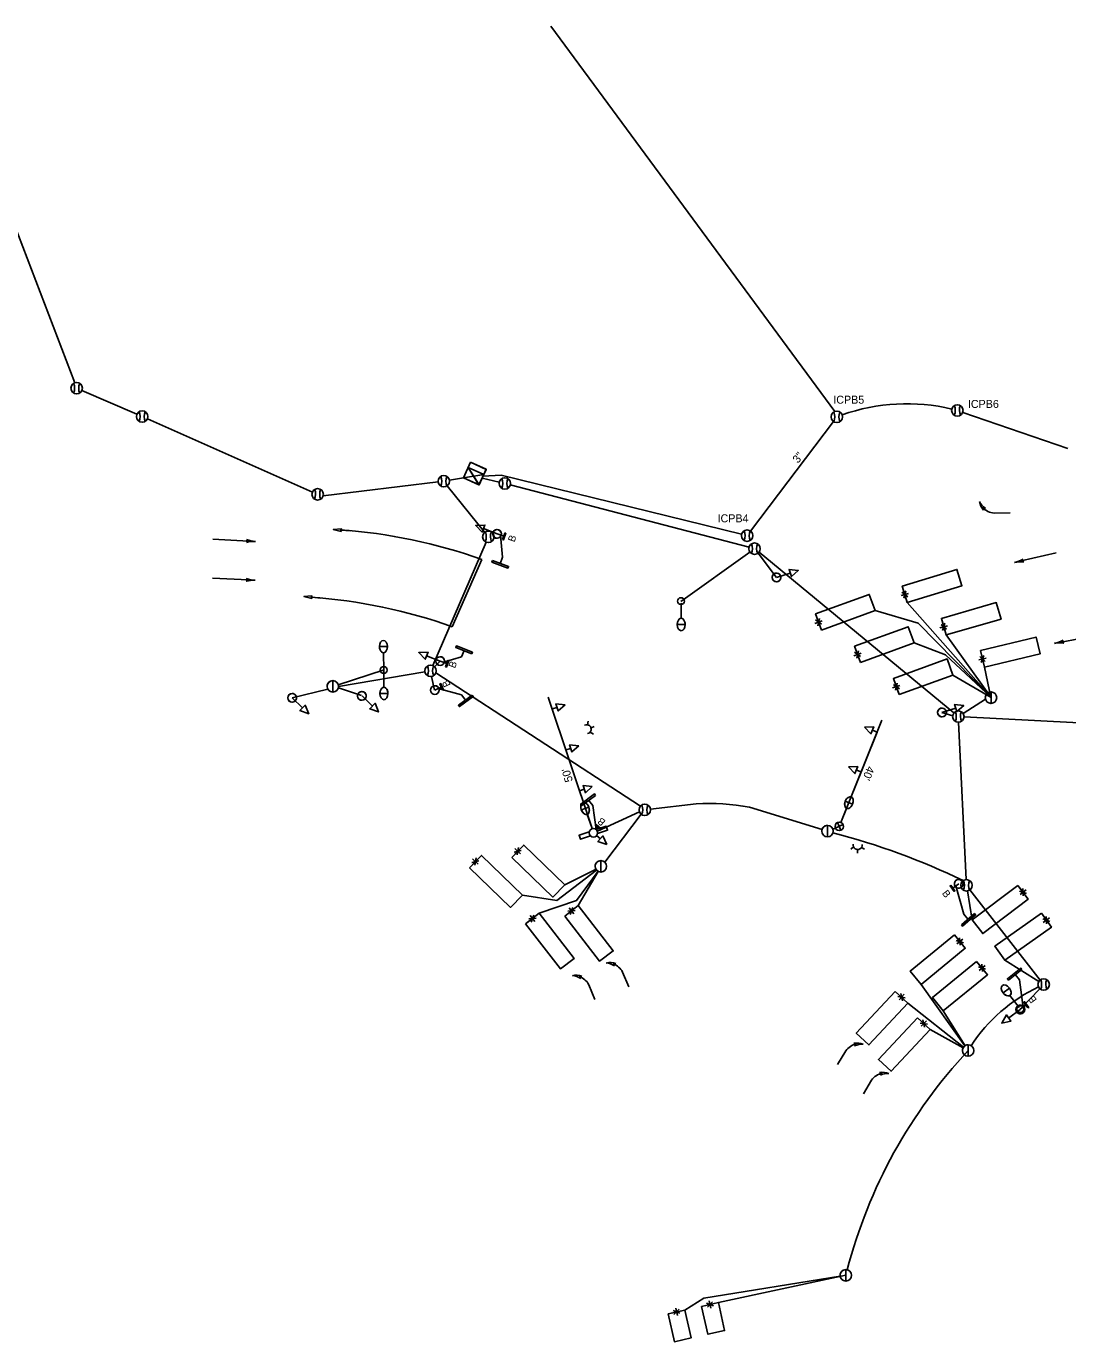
# Model space of a CAD drawing. Extents: x 596176 to 605330, y 332416 to 402398.
# Drawn here: x 603963.9 to 604328.3, y 349684.1 to 350144.4 of the extents above; entities that cross this region are included whole.
import ezdxf

# ---------------------------------------------------------------- set-up
doc = ezdxf.new("R2010")
doc.units = 0
for name, color, linetype in [('P_LTG', 7, 'Continuous'), ('P_SIG', 7, 'Continuous'), ('P_SIG_Bold', 7, 'Continuous'), ('P_SIG_Conduit', 7, 'Continuous'), ('P_SIG_IC', 7, 'Continuous'), ('P_SIG_Loops', 7, 'Continuous'), ('P_SIG_SignalHeads', 7, 'Continuous')]:
    doc.layers.add(name, color=color, linetype=linetype)

# ---------------------------------------------------------------- blocks, each defined once
blk = doc.blocks.new('_U260')
at = {"layer": 'P_SIG'}
blk.add_line((-0.385, 0.001), (0, 0), dxfattribs=at)
for points in [[(-0.611, 0.001), (-0.385, 0.101), (-0.385, -0.1), (-0.611, 0.001)], [(-0.385, 0.101), (-0.611, 0.001), (-0.385, -0.1), (-0.385, 0.101)], [(-0.611, 0.001), (-0.385, 0.101), (-0.385, -0.1), (-0.611, 0.001)]]:
    blk.add_lwpolyline(points, dxfattribs=at)
blk = doc.blocks.new('_U244')
at = {"layer": 'P_SIG'}
blk.add_circle((0, 0), 0.116, dxfattribs=at)
for start, end in [(0, 180), (180, 0)]:
    blk.add_arc((0, 0), 0.116, start, end, dxfattribs=at)
blk = doc.blocks.new('_U247')
at = {"layer": 'P_SIG_Bold'}
for p, q in [((-3.048, 0), (-0.114, 0)), ((-0.081, 0.081), (0.081, -0.081)), ((0.081, 0.081), (-0.081, -0.081))]:
    blk.add_line(p, q, dxfattribs=at)
blk.add_circle((0, 0), 0.114, dxfattribs=at)
blk.add_text("40'", height=0.2134, dxfattribs=at).set_placement((-1.787, 0.092))
blk = doc.blocks.new('_U248')
at = {"layer": 'P_SIG_Bold'}
blk.add_line((-0.114, 0), (-3.81, 0), dxfattribs=at)
for points in [[(-0.057, 0.098), (-0.057, 0.38), (0.058, 0.38), (0.058, 0.098)], [(0.058, -0.1), (0.058, -0.382), (-0.057, -0.382), (-0.057, -0.1)]]:
    blk.add_lwpolyline(points, dxfattribs=at)
blk.add_circle((0.001, -0.001), 0.114, dxfattribs=at)
at = {"layer": 'P_SIG'}
blk.add_text("50'", height=0.2134, rotation=178.0381, dxfattribs=at).set_placement((-1.484, -0.08))
blk = doc.blocks.new('LUMINAIRES_1')
at = {"layer": 'P_LTG'}
for p, q in [((4.3, 25.1), (-4.1, 25.1)), ((0, 2.3), (0, 18.4))]:
    blk.add_line(p, q, dxfattribs=at)
blk.add_circle((0, 0.1), 3.68, dxfattribs=at)
blk.add_ellipse((0.1, 25.1), major_axis=(0, 6.65), ratio=0.636439, dxfattribs=at)
blk.add_ellipse((0.1, 25.1), major_axis=(0, 6.65), ratio=0.636439, start_param=1.570796, end_param=4.712389, dxfattribs=at)
blk = doc.blocks.new('_U249')
at = {"layer": 'P_LTG'}
for p, q in [((4.3, 25.1), (-4.1, 25.1)), ((0, 2.3), (0, 18.4))]:
    blk.add_line(p, q, dxfattribs=at)
blk.add_ellipse((0.1, 25.1), major_axis=(0, 6.65), ratio=0.636439, dxfattribs=at)
blk.add_ellipse((0.1, 25.1), major_axis=(0, 6.65), ratio=0.636439, start_param=1.570796, end_param=4.712389, dxfattribs=at)
blk = doc.blocks.new('HEAD - TEMPORARY_2')
at = {"layer": 'P_SIG'}
blk.add_line((0.135, 0), (0, 0), dxfattribs=at)
blk.add_lwpolyline([(0.36, 0), (0.135, -0.1), (0.135, 0.1)], close=True, dxfattribs=at)
blk = doc.blocks.new('PUSH BUTTON')
at = {"layer": 'P_SIG'}
blk.add_line((0, 0), (7.6, 0), dxfattribs=at)
blk.add_lwpolyline([(7.6, -3.7), (7.6, 3.7), (8.6, 3.7), (8.6, -3.7)], close=True, dxfattribs=at)
blk.add_text('B', height=7.68, rotation=90, dxfattribs=at).set_placement((20.6, -2.6))
blk = doc.blocks.new('CONTROL CABINET_3')
at = {"layer": 'P_SIG'}
for p, q in [((-0.114, 0.076), (0.114, 0.076)), ((-0.114, 0.076), (0.114, -0.076)), ((0.114, 0.076), (-0.114, -0.076))]:
    blk.add_line(p, q, dxfattribs=at)
blk.add_lwpolyline([(-0.114, 0.152), (0.114, 0.152), (0.114, -0.076), (-0.114, -0.076)], close=True, dxfattribs=at)
blk = doc.blocks.new('_U256')
at = {"layer": 'P_SIG_Loops'}
for p, q in [((-0.055, -0.084), (0.052, 0.081)), ((0.056, -0.083), (-0.053, 0.082)), ((0, 0), (0, -0.229)), ((-0.105, -0.001), (0.099, -0.001))]:
    blk.add_line(p, q, dxfattribs=at)
blk.add_lwpolyline([(0, -0.229), (1.524, -0.229), (1.524, 0.229), (0, 0.229)], close=True, dxfattribs=at)
blk = doc.blocks.new('_U257')
at = {"layer": 'P_SIG_Loops'}
for p, q in [((-0.055, -0.084), (0.052, 0.081)), ((0.056, -0.083), (-0.053, 0.082)), ((-0.105, -0.001), (0.099, -0.001))]:
    blk.add_line(p, q, dxfattribs=at)
blk.add_lwpolyline([(0, -0.229), (0.762, -0.229), (0.762, 0.229), (0, 0.229)], close=True, dxfattribs=at)
blk = doc.blocks.new('_U212')
at = {"layer": 'P_SIG'}
blk.add_circle((0, 0), 6.1, dxfattribs=at)
for centre, start, end in [((-15.5, 0.1), 336.6741, 22.5272), ((15.5, 0.1), 157.5751, 203.4282)]:
    blk.add_arc(centre, 13.3, start, end, dxfattribs=at)
blk = doc.blocks.new('_U211')
at = {"layer": 'P_SIG'}
blk.add_line((0, 6.1), (0, -6.1), dxfattribs=at)
blk.add_lwpolyline([(0, -6.1), (0, 6.1)], dxfattribs=at)
blk.add_circle((0, 0), 6.1, dxfattribs=at)
for start, end in [(89.7008, 180), (180, 269.7008)]:
    blk.add_arc((0, 0), 6.1, start, end, dxfattribs=at)
blk = doc.blocks.new('_U269')
at = {"layer": 'P_SIG'}
blk.add_line((-0.017, -0.02), (-0.975, -0.02), dxfattribs=at)
blk.add_lwpolyline([(-0.914, 0.018), (-0.975, -0.02), (-0.914, -0.058)], dxfattribs=at)
for centre, start, end in [((-1.158, 0.78), 270, 287.7623), ((-1.158, -0.819), 72.2377, 90)]:
    blk.add_arc(centre, 0.799, start, end, dxfattribs=at)
blk = doc.blocks.new('_U268')
at = {"layer": 'P_SIG'}
for p, q in [((-0.675, 0.115), (-0.743, 0.129)), ((-0.725, 0.057), (-0.743, 0.129)), ((-0.017, -0.02), (-0.443, -0.02))]:
    blk.add_line(p, q, dxfattribs=at)
for centre, radius, start, end in [((-0.479, 0.454), 0.392, 205.2667, 239.9151), ((-0.377, 0.361), 0.462, 189.3153, 221.1715), ((-0.412, 0.421), 0.442, 221.4708, 266.0347)]:
    blk.add_arc(centre, radius, start, end, dxfattribs=at)
blk = doc.blocks.new('_U270')
at = {"layer": 'P_SIG'}
for p, q in [((-0.725, -0.096), (-0.743, -0.168)), ((-0.675, -0.154), (-0.743, -0.168)), ((-0.017, -0.02), (-0.443, -0.02))]:
    blk.add_line(p, q, dxfattribs=at)
for centre, radius, start, end in [((-0.377, -0.401), 0.462, 138.8285, 170.6847), ((-0.479, -0.493), 0.392, 120.0849, 154.7333), ((-0.412, -0.46), 0.442, 93.9653, 138.5292)]:
    blk.add_arc(centre, radius, start, end, dxfattribs=at)
blk = doc.blocks.new('CONFIRMATION LIGHT_1')
at = {"layer": 'P_SIG'}
for p, q in [((-4.2, 3), (-7.5, 4.8)), ((0, 5.5), (0, 9.2)), ((4.3, 2.9), (7.3, 5.5))]:
    blk.add_line(p, q, dxfattribs=at)
blk.add_arc((0, 0.6), 4.81, 352.2462, 187.7538, dxfattribs=at)
blk = doc.blocks.new('_U280')
at = {"layer": 'P_LTG'}
for p, q in [((4.3, 25), (-4.2, 25)), ((0, 0), (0, 18.5)), ((0, 0), (0, -18.3)), ((-4.3, -25), (4.2, -25))]:
    blk.add_line(p, q, dxfattribs=at)
blk.add_circle((0, 0), 3.68, dxfattribs=at)
for centre, major_axis in [((0, 25), (0, 6.65)), ((0, -25), (0, -6.65))]:
    blk.add_ellipse(centre, major_axis=major_axis, ratio=0.636439, dxfattribs=at)
for centre, major_axis in [((0, 25), (0, 6.65)), ((0, -25), (0, -6.65))]:
    blk.add_ellipse(centre, major_axis=major_axis, ratio=0.636439, start_param=1.570796, end_param=4.712389, dxfattribs=at)
blk = doc.blocks.new('CONTROL CABINET_4')
at = {"layer": 'P_SIG'}
for p, q in [((-0.114, 0.076), (0.114, 0.076)), ((-0.114, 0.076), (0.114, -0.076)), ((0.114, 0.076), (-0.114, -0.076))]:
    blk.add_line(p, q, dxfattribs=at)
blk.add_lwpolyline([(-0.114, 0.152), (0.114, 0.152), (0.114, -0.076), (-0.114, -0.076)], close=True, dxfattribs=at)

msp = doc.modelspace()

# ---------------------------------------------------------------- linework, layer by layer
at = {"layer": 'P_SIG'}
for p, q in [((604130.57, 349958.59), (604129.79, 349966.36)), ((604130.57, 349958.59), (604129.73, 349956.35)), ((604116.18, 349923.79), (604117.06, 349926.02)), ((604108.68, 349922.29), (604111.02, 349921.41)), ((604116.18, 349923.79), (604109.85, 349921.85)), ((604106.83, 349912.14), (604109.1, 349913.17)), ((604116.21, 349910.43), (604107.96, 349912.65)), ((604116.21, 349910.43), (604117.64, 349908.5)), ((604253.19, 349876.5), (604261.57, 349897.38)), ((604162.08, 349871.7), (604160.65, 349873.63)), ((604162.08, 349871.7), (604163.31, 349863.35)), ((604163.31, 349863.35), (604163.97, 349864.1)), ((604291.89, 349833.65), (604289.16, 349843.57)), ((604291.89, 349833.65), (604293.43, 349831.81)), ((604311.36, 349810.71), (604309.88, 349812.6)), ((604311.36, 349810.71), (604312.75, 349801.06))]:
    msp.add_line(p, q, dxfattribs=at)
for points in [[(604127.01, 349957.51), (604132.63, 349955.4), (604132.42, 349954.84), (604126.8, 349956.95)], [(604119.76, 349924.81), (604114.18, 349927.01), (604114.4, 349927.57), (604119.99, 349925.37)], [(604110.59, 349920.28), (604111.44, 349922.53), (604111.74, 349922.41), (604110.9, 349920.17)], [(604109.6, 349912.07), (604108.61, 349914.26), (604108.91, 349914.39), (604109.89, 349912.21)], [(604119.94, 349910.37), (604115.11, 349906.8), (604115.47, 349906.32), (604120.29, 349909.89)], [(604163.11, 349875.27), (604158.28, 349871.72), (604157.93, 349872.2), (604162.76, 349875.76)], [(604164.87, 349863.31), (604163.07, 349864.89), (604163.28, 349865.13), (604165.09, 349863.55)], [(604291.08, 349830.01), (604295.67, 349833.88), (604296.06, 349833.42), (604291.47, 349829.55)], [(604312.29, 349814.32), (604307.57, 349810.61), (604307.2, 349811.08), (604311.92, 349814.79)]]:
    msp.add_lwpolyline(points, close=True, dxfattribs=at)
at = {"layer": 'P_SIG_Conduit'}
for p, q in [((603980.86, 350019.67), (603946.93, 350108.38)), ((604111.94, 349985.55), (604116.93, 349986.41)), ((604106.15, 349920.71), (604124.79, 349963.92)), ((604192.95, 349943.17), (604217.11, 349960.45)), ((604219.95, 349960.02), (604226.39, 349951.56)), ((604073.08, 349913.99), (604089.08, 349919.26)), ((604108.68, 349922.29), (604106.75, 349920.31)), ((604106.78, 349912.12), (604105.71, 349916.91)), ((604056.98, 349909.4), (604069.4, 349912.46)), ((604073.09, 349912.9), (604081.15, 349910.21)), ((604291.7, 349903.92), (604299.52, 349908.95)), ((604284.3, 349904.3), (604288.04, 349903.12))]:
    msp.add_line(p, q, dxfattribs=at)
for points in [[(604002.62, 350008.65), (603983.37, 350017)], [(604064.03, 349981.44), (604006.28, 350007.04)], [(604107.98, 349984.97), (604067.79, 349980.13)], [(604129.38, 349984.91), (604123.4, 349986.31)], [(604133.26, 349983.95), (604216.8, 349962.12)], [(604124.33, 349967.32), (604111.22, 349983.65)], [(604220.28, 349960.34), (604288.47, 349904.11)], [(604073.16, 349913.43), (604103.38, 349918.55)], [(604178.78, 349871.52), (604107.24, 349918.2)], [(604290.11, 349900.84), (604292.75, 349845.79)], [(604292.01, 349902.73), (604397.1, 349897.32)], [(604178.42, 349869.5), (604163.72, 349862.77)], [(604179.05, 349868.64), (604166.34, 349851.87)], [(604182.27, 349870.5), (604198.27, 349872.32)], [(604216.98, 349871.12), (604242.33, 349863.33)], [(604246.13, 349863.45), (604247, 349863.78)], [(604294.07, 349842.22), (604318.65, 349810.64)], [(604318.51, 349807.62), (604311.65, 349800.39)]]:
    msp.add_lwpolyline(points, dxfattribs=at)
for centre, radius, start, end in [((604202.76, 349795.81), 76.64, 79.3075, 93.3542), ((604185.94, 349627.99), 241.78, 64.0669, 75.5796), ((604342.64, 349756.31), 57.45, 115.3257, 146.943), ((604423.75, 349664.09), 178.42, 136.9226, 165.3437)]:
    msp.add_arc(centre, radius, start, end, dxfattribs=at)
at = {"layer": 'P_SIG_IC'}
for points in [[(604246.84, 350009.64), (604147.46, 350144.44)], [(604291.54, 350009.29), (604328.28, 349996.72)], [(604217.31, 349967.77), (604246.3, 350006.16)], [(604123.7, 349986.96), (604130, 349987.37), (604214.16, 349966.67)]]:
    msp.add_lwpolyline(points, dxfattribs=at)
msp.add_arc((604272.03, 349944.21), 68.12, 76.6758, 109.4161, dxfattribs=at)
at = {"layer": 'P_SIG_Loops'}
for p, q in [((604123.26, 349957.84), (604112.95, 349934.29)), ((604293.18, 349841.82), (604294.91, 349831.65)), ((604306.23, 349817.56), (604318.18, 349810.12))]:
    msp.add_line(p, q, dxfattribs=at)
for points in [[(604074.08, 349967.68), (604071.32, 349968.37), (604074.15, 349968.61)], [(604063.77, 349944.13), (604061.02, 349944.82), (604063.85, 349945.06)]]:
    msp.add_lwpolyline(points, close=True, dxfattribs=at)
for points in [[(604074.11, 349968.15), (604077.24, 349967.89)], [(604063.81, 349944.59), (604066.93, 349944.34)], [(604272.16, 349942.74), (604301.45, 349909.48)], [(604260.93, 349939.98), (604275.94, 349935.59), (604301.45, 349909.48)], [(604274.57, 349928.67), (604285.5, 349924.46), (604301.45, 349909.47)], [(604285.75, 349931.41), (604301.45, 349909.48)], [(604299.19, 349920.09), (604301.44, 349909.48)], [(604288.14, 349917.38), (604301.45, 349909.48)], [(604163.47, 349849.09), (604149.56, 349838.48), (604137.52, 349840.38)], [(604143.38, 349834.02), (604156.42, 349838.48), (604163.97, 349848.7)], [(604152.33, 349843.97), (604163.24, 349849.39)], [(604157.05, 349836.71), (604164.02, 349848.67)], [(604292.27, 349787.58), (604276.99, 349809.11)], [(604272.35, 349802.59), (604291.85, 349787.19)], [(604284.75, 349799.85), (604292.37, 349787.65)], [(604280.12, 349793.33), (604291.68, 349786.92)], [(604248.66, 349706.98), (604201, 349699.26), (604194.36, 349695.13)], [(604206.07, 349697.73), (604250.64, 349707.3)]]:
    msp.add_lwpolyline(points, dxfattribs=at)
for centre in [(604061.51, 349785.54), (604051.21, 349761.98)]:
    msp.add_arc(centre, 183.03, 70.2859, 86.1613, dxfattribs=at)

# ---------------------------------------------------------------- block references
at = {"layer": 'P_LTG'}
for name, p, xscale, yscale, rotation in [('LUMINAIRES_1', (604192.97, 349943.29), 0.3280833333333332, 0.32808333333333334, -179.14755096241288), ('_U280', (604088.96, 349919.15), 0.32808333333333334, 0.3280833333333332, -179.40361482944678), ('_U249', (604162.11, 349862.92), 0.3280833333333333, 0.32808333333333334, 19.32575717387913), ('_U249', (604248.61, 349865.13), 0.3280833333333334, 0.32808333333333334, -22.19330309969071), ('LUMINAIRES_1', (604311.73, 349800.43), 0.3280833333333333, 0.32808333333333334, 37.30974535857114)]:
    msp.add_blockref(name, p, dxfattribs=dict(at, xscale=xscale, yscale=yscale, rotation=rotation))
at = {"layer": 'P_SIG'}
for name, p, xscale, yscale, rotation in [('CONTROL CABINET_4', (604120.42, 349987.01), 26.285724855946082, 26.285724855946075, -24.747018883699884), ('CONTROL CABINET_3', (604120.42, 349987.01), 26.246666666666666, 26.246666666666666, -24.669234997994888), ('CONTROL CABINET_4', (604120.42, 349987.01), 26.24666666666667, 26.24666666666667, -24.846750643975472), ('_U268', (604308.35, 349974.38), 13.123333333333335, 13.123333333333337, 0.29033250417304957), ('_U260', (604128.61, 349966.78), 13.123333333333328, 13.12333333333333, -21.48301689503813), ('_U269', (604028.94, 349964.67), 13.123333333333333, 13.123333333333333, 177.08051879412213), ('_U244', (604128.61, 349966.78), 13.123333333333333, 13.123333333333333, 160.85244389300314), ('PUSH BUTTON', (604128.61, 349966.78), 0.32808333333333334, 0.32808333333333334, -19.438543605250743), ('_U269', (604324.43, 349960.48), 13.123333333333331, 13.123333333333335, 13.149163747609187), ('_U269', (604028.84, 349951.06), 13.123333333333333, 13.123333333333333, 177.08051879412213), ('_U244', (604226.39, 349951.56), 13.123333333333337, 13.123333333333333, -162.1158384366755), ('_U260', (604226.39, 349951.56), 13.123333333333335, 13.123333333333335, -162.1158384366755), ('_U269', (604338.54, 349931.52), 13.123333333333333, 13.123333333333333, 10.52994057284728), ('_U260', (604108.68, 349922.29), 13.123333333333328, 13.12333333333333, -21.48301689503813), ('_U244', (604108.68, 349922.29), 13.123333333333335, 13.123333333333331, -21.64588104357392), ('_U244', (604056.92, 349909.4), 13.123333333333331, 13.123333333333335, 136.489148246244), ('_U260', (604056.96, 349909.41), 13.123333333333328, 13.12333333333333, 135.88695012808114), ('_U244', (604081.34, 349910.06), 13.123333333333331, 13.123333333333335, 136.489148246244), ('_U260', (604081.38, 349910.07), 13.123333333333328, 13.12333333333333, 135.88695012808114), ('_U244', (604106.83, 349912.14), 13.123333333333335, 13.123333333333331, -21.64588104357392), ('_U248', (604162.33, 349862.21), 13.123333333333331, 13.123333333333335, -71.60358121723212), ('HEAD - TEMPORARY_2', (604147.93, 349905.52), 13.123333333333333, 13.123333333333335, 17.99154968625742), ('_U244', (604284.3, 349904.3), 13.123333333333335, 13.123333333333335, -162.1158384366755), ('_U260', (604284.3, 349904.3), 13.123333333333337, 13.123333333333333, -162.11583843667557), ('_U247', (604248.36, 349864.43), 13.123333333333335, 13.123333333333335, -111.8527022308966), ('HEAD - TEMPORARY_2', (604261.57, 349897.38), 13.123333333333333, 13.123333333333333, 157.76758633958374), ('HEAD - TEMPORARY_2', (604152.7, 349891.16), 13.123333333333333, 13.123333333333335, 17.99154968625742), ('HEAD - TEMPORARY_2', (604255.99, 349883.46), 13.123333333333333, 13.123333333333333, 157.76758633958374), ('HEAD - TEMPORARY_2', (604157.44, 349876.92), 13.123333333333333, 13.123333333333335, 17.99154968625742), ('HEAD - TEMPORARY_2', (604163.46, 349861.23), 13.123333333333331, 13.123333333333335, -40.99852585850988), ('_U244', (604290.14, 349844.31), 13.123333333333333, 13.123333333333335, 36.20208107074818), ('PUSH BUTTON', (604290.14, 349844.31), 0.3280833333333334, 0.32808333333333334, -143.74221098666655), ('_U270', (604175.01, 349808.17), 13.123333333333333, 13.123333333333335, -67.28010227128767), ('_U270', (604163.17, 349803.74), 13.123333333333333, 13.123333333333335, -67.28010227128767), ('PUSH BUTTON', (604311.65, 349800.39), 0.32808333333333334, 0.3280833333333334, 36.25778901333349), ('_U260', (604311.7, 349800.33), 13.12333333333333, 13.123333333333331, 36.23789948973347), ('_U244', (604311.71, 349800.34), 13.123333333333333, 13.123333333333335, 36.20208107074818), ('_U268', (604247.89, 349780.73), 13.12333333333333, 13.123333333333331, -120.95667219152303), ('_U268', (604256.9, 349770.5), 13.12333333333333, 13.123333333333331, -120.95667219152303)]:
    msp.add_blockref(name, p, dxfattribs=dict(at, xscale=xscale, yscale=yscale, rotation=rotation))
at = {"layer": 'P_SIG_Conduit', "xscale": 0.32808333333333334, "yscale": 0.32808333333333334}
for name, p in [('_U212', (603981.53, 350017.78)), ('_U212', (604004.46, 350007.85)), ('_U212', (604109.97, 349985.21)), ('_U212', (604131.33, 349984.45)), ('_U212', (604065.85, 349980.62)), ('_U212', (604125.58, 349965.76)), ('_U212', (604218.73, 349961.61)), ('_U212', (604105.36, 349918.87)), ('_U211', (604071.16, 349913.42)), ('_U211', (604301.45, 349909.47)), ('_U212', (604290.02, 349902.84)), ('_U212', (604180.29, 349870.2)), ('_U211', (604244.25, 349862.77)), ('_U211', (604164.94, 349850.45)), ('_U212', (604292.84, 349843.79)), ('_U212', (604319.88, 349809.06)), ('_U211', (604293.42, 349785.95)), ('_U211', (604250.64, 349707.3))]:
    msp.add_blockref(name, p, dxfattribs=at)
at = {"layer": 'P_SIG_IC', "xscale": 0.32808333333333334, "yscale": 0.32808333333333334}
for p in [(604289.67, 350010), (604247.51, 350007.76), (604216.1, 349966.17)]:
    msp.add_blockref('_U212', p, dxfattribs=at)
at = {"layer": 'P_SIG_Loops'}
for name, p, xscale, yscale, rotation in [('_U256', (604271.28, 349945.61), 13.123333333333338, 13.123333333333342, 17.156179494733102), ('_U256', (604241.11, 349935.94), 13.123333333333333, 13.123333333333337, 20.049305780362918), ('_U256', (604284.92, 349934.29), 13.123333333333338, 13.123333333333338, 16.092772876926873), ('_U256', (604254.75, 349924.63), 13.123333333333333, 13.123333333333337, 20.049305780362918), ('_U256', (604298.49, 349923.01), 13.123333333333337, 13.123333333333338, 13.642930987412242), ('_U256', (604268.32, 349913.35), 13.123333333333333, 13.123333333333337, 20.049305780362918), ('_U256', (604121.06, 349852.12), 13.12333333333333, 13.12333333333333, -44.04414256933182), ('_U256', (604135.87, 349855.72), 13.12333333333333, 13.12333333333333, -44.04414256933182), ('_U256', (604312.65, 349841.37), 13.123333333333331, 13.12333333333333, -142.7570431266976), ('_U256', (604154.67, 349834.88), 13.12333333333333, 13.12333333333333, -52.42903853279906), ('_U256', (604141.01, 349832.19), 13.12333333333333, 13.12333333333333, -52.42903853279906), ('_U256', (604320.82, 349831.56), 13.12333333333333, 13.12333333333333, -144.7199303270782), ('_U256', (604290.56, 349824.09), 13.123333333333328, 13.12333333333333, -140.7002047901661), ('_U256', (604298.33, 349814.84), 13.123333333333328, 13.12333333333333, -140.7002047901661), ('_U256', (604270.16, 349804.63), 13.123333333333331, 13.12333333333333, -133.05283831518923), ('_U256', (604277.92, 349795.38), 13.123333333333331, 13.12333333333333, -133.05283831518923), ('_U257', (604203.14, 349697.08), 13.123333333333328, 13.12333333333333, -77.46116857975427), ('_U257', (604191.43, 349694.48), 13.123333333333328, 13.12333333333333, -77.46116857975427)]:
    msp.add_blockref(name, p, dxfattribs=dict(at, xscale=xscale, yscale=yscale, rotation=rotation))
at = {"layer": 'P_SIG_SignalHeads', "yscale": 0.32808333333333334}
for p, xscale, rotation in [((604159.81, 349898.36), 0.3280833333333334, -70.40606078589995), ((604254.82, 349858.1), 0.3280833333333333, 177.64680052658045)]:
    msp.add_blockref('CONFIRMATION LIGHT_1', p, dxfattribs=dict(at, xscale=xscale, rotation=rotation))

# ---------------------------------------------------------------- texts
at = {"layer": 'P_SIG'}
for rotation, p in [(69.3557, (604113.89, 349919.58)), (114.295, (604112.44, 349913.86)), (138.8667, (604166.8, 349866.24))]:
    msp.add_text('B', height=2.52, rotation=rotation, dxfattribs=at).set_placement(p)
at = {"layer": 'P_SIG_IC'}
for s, p in [('ICPB5', (604246.27, 350012.36)), ('ICPB6', (604293.37, 350010.87)), ('ICPB4', (604205.78, 349970.84))]:
    msp.add_text(s, height=2.8, dxfattribs=at).set_placement(p)
msp.add_text('3"', height=2.8, rotation=51.946, dxfattribs=at).set_placement((604233.95, 349991.33))

doc.saveas('drawing.dxf')
